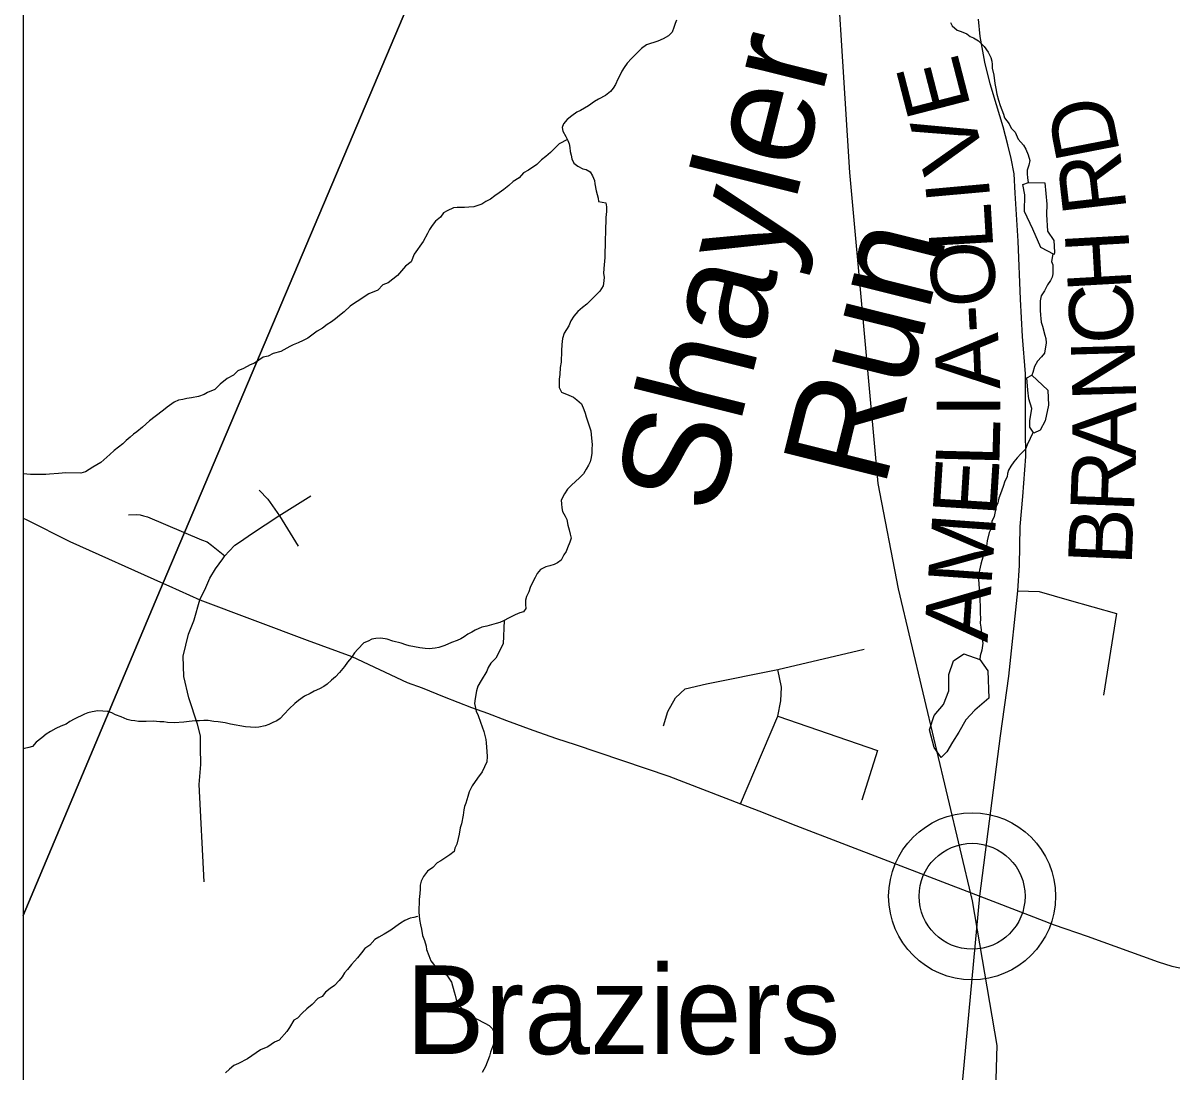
# Model space of a CAD drawing. Extents: x 0 to 34, y 0 to 22.
# Drawn here: x 2.1 to 3.128, y 15.954 to 16.889 of the extents above; entities that cross this region are included whole.
import ezdxf

# ---------------------------------------------------------------- set-up
doc = ezdxf.new("R2010")
doc.units = 0
for name, color, linetype in [('GM_X_Corporation', 7, 'Continuous'), ('GM_X_County_Road', 7, 'Continuous'), ('GM_X_County_Road_Text', 7, 'Continuous'), ('GM_X_Minor_Lake', 7, 'Continuous'), ('GM_X_Minor_River', 7, 'Continuous'), ('GM_X_Minor_River_Text', 7, 'Continuous'), ('GM_X_Rail_Line', 7, 'Continuous'), ('GM_X_Township_Road', 7, 'Continuous'), ('GM_X_Unincorporated', 7, 'Continuous'), ('GM_X_Unincorporated_Location', 7, 'Continuous'), ('GM_X_Unincorporated_Text', 7, 'Continuous'), ('SH_Data', 7, 'Continuous')]:
    doc.layers.add(name, color=color, linetype=linetype)

msp = doc.modelspace()

# ---------------------------------------------------------------- linework, layer by layer
at = {"layer": 'GM_X_Corporation'}
for points in [[(2.1, 20.9), (2.1, 16.0934), (2.225, 16.3897), (2.7544, 17.639), (2.811, 17.7726), (2.8255, 17.8068), (2.8709, 17.914), (2.886, 17.9497), (2.8909, 17.9612), (2.9719, 18.1533), (3.7872, 20.088)], [(3.7872, 20.088), (2.9719, 18.1533), (2.8909, 17.9612), (2.886, 17.9497), (2.8709, 17.914), (2.8255, 17.8068), (2.811, 17.7726), (2.7544, 17.639), (2.225, 16.3897), (2.1, 16.0934), (2.1, 14.8365)]]:
    msp.add_lwpolyline(points, dxfattribs=at)
at = {"layer": 'GM_X_County_Road'}
for points in [[(2.953, 16.1107), (2.9713, 16.2535), (2.9786, 16.3067), (2.9868, 16.3825), (2.9883, 16.4053), (2.9889, 16.4399), (2.9913, 16.4668), (2.9939, 16.5023), (2.9936, 16.5265), (2.9936, 16.576), (2.9909, 16.6092), (2.9892, 16.6426), (2.9872, 16.6943), (2.9843, 16.737), (2.9835, 16.7541), (2.9808, 16.7677), (2.9778, 16.78), (2.9736, 16.7961), (2.9676, 16.8156), (2.9621, 16.8344), (2.9574, 16.8538), (2.9532, 16.8765), (2.9518, 16.8919)], [(2.1, 16.4475), (2.1029, 16.4462), (2.1416, 16.4265), (2.2252, 16.3892), (2.2298, 16.3871)], [(2.2298, 16.3871), (2.2576, 16.3747), (2.3533, 16.3387), (2.393, 16.3242), (2.4425, 16.3011), (2.4557, 16.2962), (2.4755, 16.2881), (2.4998, 16.2786), (2.5139, 16.2735), (2.531, 16.2671), (2.5545, 16.2586), (2.5755, 16.251), (2.5922, 16.2458), (2.6756, 16.2174), (2.7395, 16.193), (2.7558, 16.1866), (2.7889, 16.1737), (2.953, 16.1107)], [(2.8829, 15.4935), (2.8842, 15.5063), (2.8874, 15.5358), (2.894, 15.5961), (2.8994, 15.6456), (2.9147, 15.7602), (2.9206, 15.7916), (2.9222, 15.8054), (2.9252, 15.8145), (2.9273, 15.8275), (2.9285, 15.8425), (2.9327, 15.8893), (2.9339, 15.9077), (2.9364, 15.9344), (2.953, 16.1107)], [(2.953, 16.1107), (2.997, 16.0938), (3.0192, 16.0852), (3.0486, 16.0749), (3.1119, 16.0522), (3.1239, 16.0483), (3.1311, 16.0466)]]:
    msp.add_lwpolyline(points, dxfattribs=at)
at = {"layer": 'GM_X_Minor_Lake'}
for points in [[(2.9927, 16.7207), (2.993, 16.7355), (2.9912, 16.7446), (2.9962, 16.7465)], [(2.996, 16.7465), (3.0107, 16.7462), (3.0126, 16.7272), (3.0124, 16.718), (3.0133, 16.7032), (3.0189, 16.6948), (3.0195, 16.6845), (3.0191, 16.6822), (3.0074, 16.6885), (3, 16.705), (2.9927, 16.7207)], [(2.9975, 16.5341), (2.9992, 16.545), (2.9967, 16.5538), (2.9957, 16.5614), (2.9947, 16.5725), (2.9993, 16.5748)], [(2.9993, 16.5748), (3.0135, 16.5615), (3.0141, 16.5482), (3.0112, 16.5342), (3.0068, 16.5259), (3.0011, 16.523), (2.9974, 16.5284), (2.9975, 16.5341)], [(2.9528, 16.3215), (2.9601, 16.3114), (2.9608, 16.287), (2.9485, 16.2762), (2.9403, 16.2676), (2.9341, 16.2567), (2.9286, 16.2477), (2.9235, 16.2391), (2.9185, 16.2342), (2.9121, 16.2431), (2.9079, 16.2587), (2.9123, 16.2716), (2.9204, 16.2813), (2.9252, 16.2934), (2.9254, 16.3082)], [(2.9254, 16.3082), (2.9295, 16.3202), (2.9387, 16.3265), (2.9528, 16.3215)]]:
    msp.add_lwpolyline(points, dxfattribs=at)
at = {"layer": 'GM_X_Minor_River'}
for points in [[(2.6825, 16.8911), (2.6814, 16.8881), (2.6802, 16.8847), (2.6786, 16.8805), (2.6755, 16.8771), (2.6705, 16.8746), (2.6659, 16.8724), (2.6556, 16.8691), (2.6513, 16.8658), (2.6475, 16.862), (2.6424, 16.8568), (2.6386, 16.8527), (2.6358, 16.8489), (2.6339, 16.8456), (2.6319, 16.8418), (2.6303, 16.8384), (2.628, 16.8339), (2.626, 16.8305), (2.6237, 16.8275), (2.6191, 16.8241), (2.6129, 16.8208), (2.6095, 16.8186), (2.6041, 16.8149), (2.5968, 16.8105), (2.5937, 16.809), (2.5891, 16.806), (2.5849, 16.8027), (2.5818, 16.7986), (2.5806, 16.7955), (2.5813, 16.7921), (2.5839, 16.7875), (2.5857, 16.784), (2.5868, 16.781), (2.5875, 16.7776), (2.5878, 16.7741), (2.5885, 16.7707), (2.5892, 16.7676), (2.5911, 16.7638), (2.5944, 16.7611), (2.599, 16.7587), (2.602, 16.7579), (2.6054, 16.756)], [(2.9266, 16.8891), (2.9281, 16.886), (2.9326, 16.8822), (2.9363, 16.8809), (2.9412, 16.879), (2.9443, 16.8766), (2.9473, 16.8754), (2.9518, 16.8727), (2.9566, 16.8677), (2.9604, 16.8627), (2.9626, 16.8577), (2.9637, 16.8546), (2.964, 16.8516), (2.9639, 16.8482), (2.9653, 16.842), (2.9664, 16.8348), (2.967, 16.8302), (2.9681, 16.8253), (2.9695, 16.8199), (2.971, 16.815), (2.9724, 16.8111), (2.9739, 16.8073), (2.975, 16.8042), (2.9791, 16.7988), (2.9809, 16.795), (2.9843, 16.7912), (2.9872, 16.785), (2.9917, 16.7796), (2.9939, 16.7762), (2.9961, 16.7712), (2.9975, 16.7662), (2.9967, 16.762), (2.9951, 16.7575), (2.995, 16.7541), (2.9954, 16.7507), (2.996, 16.7465)], [(2.5853, 16.7849), (2.578, 16.7808), (2.5703, 16.7733), (2.5661, 16.7696), (2.5622, 16.7666), (2.558, 16.7625), (2.5507, 16.7573), (2.5461, 16.7551), (2.5422, 16.7506), (2.5368, 16.7473), (2.5329, 16.7439), (2.5287, 16.7402), (2.5245, 16.7372), (2.5206, 16.7346), (2.5168, 16.7317), (2.5126, 16.7294), (2.5091, 16.7272), (2.5018, 16.7247), (2.4973, 16.7244), (2.4935, 16.7241), (2.487, 16.7242), (2.4836, 16.7239), (2.4782, 16.7213), (2.4747, 16.7195), (2.472, 16.7157), (2.4678, 16.712), (2.4647, 16.7082), (2.4623, 16.7045), (2.4604, 16.7011), (2.4568, 16.6939), (2.4487, 16.6827), (2.4459, 16.6759), (2.4409, 16.6718), (2.4339, 16.6635), (2.4254, 16.6572), (2.4208, 16.6554), (2.4162, 16.6505), (2.4081, 16.6473), (2.4031, 16.6439), (2.3993, 16.6413), (2.3962, 16.6395), (2.3916, 16.6362), (2.3862, 16.6313), (2.382, 16.628), (2.3785, 16.625), (2.375, 16.6224), (2.3712, 16.6198), (2.367, 16.6168), (2.3623, 16.6139), (2.3539, 16.6079), (2.3497, 16.6057), (2.3451, 16.6035), (2.3408, 16.6017), (2.3378, 16.6002), (2.3297, 16.5958), (2.3229, 16.594), (2.3186, 16.5918), (2.3141, 16.5908), (2.3064, 16.5856), (2.3025, 16.5841), (2.2964, 16.5808), (2.2914, 16.5786), (2.2876, 16.5749), (2.2818, 16.5719), (2.2756, 16.5667), (2.271, 16.5619), (2.2645, 16.5593), (2.2614, 16.5575), (2.2564, 16.5557), (2.2503, 16.5546), (2.2461, 16.5539), (2.2423, 16.5532), (2.2385, 16.5525), (2.2347, 16.5507), (2.2285, 16.5463), (2.2251, 16.5437), (2.2177, 16.5381), (2.2127, 16.534), (2.2066, 16.5284), (2.2015, 16.5243), (2.1985, 16.5221), (2.1954, 16.5195), (2.1919, 16.5165), (2.1888, 16.5135), (2.1811, 16.5076), (2.1773, 16.5042), (2.1692, 16.4971), (2.1622, 16.4927), (2.1557, 16.4886), (2.1515, 16.4876), (2.1382, 16.4878), (2.1317, 16.4871), (2.1237, 16.4865), (2.1203, 16.4862), (2.1066, 16.4864), (2.1002, 16.4869), (2.1, 16.487)], [(2.6054, 16.756), (2.6076, 16.7525), (2.6094, 16.7483), (2.6098, 16.7452), (2.6108, 16.7391), (2.6126, 16.7326), (2.6129, 16.7296), (2.6163, 16.7288), (2.6194, 16.7283), (2.6201, 16.7249), (2.62, 16.7207), (2.6195, 16.7154), (2.6193, 16.7025), (2.6188, 16.6953), (2.6186, 16.6797), (2.6176, 16.6698), (2.6175, 16.6653), (2.6179, 16.6622), (2.6178, 16.6588), (2.617, 16.6543), (2.6142, 16.6497), (2.6077, 16.643), (2.6026, 16.6382), (2.5988, 16.6352), (2.5945, 16.6315), (2.5911, 16.6273), (2.5883, 16.6232), (2.5864, 16.6187), (2.5824, 16.6123), (2.5808, 16.6074), (2.5804, 16.6021), (2.5799, 16.5964), (2.5797, 16.5865), (2.5789, 16.5816), (2.5784, 16.5755), (2.578, 16.5713), (2.5778, 16.5637), (2.58, 16.5595), (2.5865, 16.5571), (2.5906, 16.5551), (2.5936, 16.5528), (2.5977, 16.5493), (2.5999, 16.5443), (2.601, 16.5409), (2.6021, 16.5378), (2.6032, 16.534), (2.605, 16.5287), (2.6061, 16.5252), (2.6064, 16.5218), (2.6067, 16.5187), (2.6074, 16.513), (2.6069, 16.5089), (2.6069, 16.5054), (2.6064, 16.5013), (2.6056, 16.4975), (2.604, 16.4945), (2.6021, 16.4911), (2.5997, 16.4869), (2.5959, 16.4832), (2.5889, 16.4769), (2.5854, 16.4731), (2.5827, 16.469), (2.5796, 16.4633), (2.5799, 16.4603), (2.5802, 16.4565), (2.5809, 16.4534), (2.5831, 16.4492), (2.5846, 16.4462), (2.5857, 16.4412), (2.5867, 16.437), (2.5878, 16.4332), (2.5885, 16.4297), (2.5873, 16.426), (2.5853, 16.4211), (2.5841, 16.4177), (2.5822, 16.4147), (2.5798, 16.4101), (2.5763, 16.4075), (2.5733, 16.4061), (2.5695, 16.405), (2.566, 16.4039), (2.5614, 16.4017), (2.5583, 16.398), (2.5564, 16.3946), (2.554, 16.3901), (2.552, 16.3855), (2.5508, 16.3818), (2.5489, 16.3776), (2.548, 16.3742), (2.548, 16.3704), (2.5483, 16.367), (2.546, 16.364), (2.5429, 16.3629), (2.5387, 16.3614), (2.5333, 16.3585), (2.5283, 16.3559), (2.5249, 16.3545), (2.5218, 16.3534), (2.5134, 16.3512), (2.5089, 16.3502), (2.5031, 16.3476)], [(3.0179, 16.6829), (3.0169, 16.6762), (3.018, 16.6731)], [(3.018, 16.6731), (3.0179, 16.6682), (3.0179, 16.6651), (3.0174, 16.6621), (3.0159, 16.6591), (3.0132, 16.6553), (3.0104, 16.65), (3.0077, 16.6455), (3.0068, 16.641), (3.0067, 16.6326), (3.007, 16.6284), (3.0073, 16.6254), (3.0076, 16.622), (3.0087, 16.6185), (3.0109, 16.6105), (3.0116, 16.6075), (3.0119, 16.6036), (3.0106, 16.5945), (3.0079, 16.5912), (3.0044, 16.5874), (3.0017, 16.5825), (3.0001, 16.5772), (2.9993, 16.5748)], [(3.0004, 16.524), (2.9952, 16.5127), (2.9936, 16.5089), (2.9893, 16.5048), (2.9862, 16.5011), (2.9831, 16.4977), (2.9804, 16.4936), (2.9784, 16.4902), (2.9776, 16.4872), (2.9772, 16.4841), (2.9752, 16.4804), (2.9736, 16.4755), (2.9712, 16.469), (2.9697, 16.4653), (2.9688, 16.4611), (2.9673, 16.4577), (2.9656, 16.449), (2.9636, 16.4445), (2.9635, 16.4407), (2.9627, 16.4376), (2.9612, 16.4346), (2.9595, 16.4271), (2.9587, 16.4225), (2.9575, 16.4191), (2.9547, 16.4097), (2.9538, 16.4063), (2.9526, 16.401), (2.9518, 16.3964), (2.9517, 16.3926), (2.952, 16.3888), (2.9526, 16.3801), (2.953, 16.3762), (2.9532, 16.3671), (2.9531, 16.3629), (2.9534, 16.3576), (2.9533, 16.3538), (2.9537, 16.3504), (2.955, 16.3393), (2.9557, 16.3359), (2.9548, 16.3298), (2.9532, 16.3246), (2.9528, 16.3215)], [(2.5289, 16.3562), (2.528, 16.3354), (2.5213, 16.3226), (2.5171, 16.3181), (2.5147, 16.3144), (2.5135, 16.311), (2.5084, 16.3027), (2.5053, 16.2978), (2.5041, 16.2936), (2.5029, 16.2868), (2.5024, 16.2823), (2.5038, 16.2754), (2.5056, 16.2716), (2.5078, 16.2655), (2.5107, 16.2574), (2.5125, 16.2502), (2.5128, 16.2471), (2.5135, 16.2395), (2.5138, 16.2349), (2.5133, 16.2304), (2.5094, 16.2213), (2.5051, 16.2157), (2.5004, 16.209), (2.4977, 16.2037), (2.4964, 16.1995), (2.4948, 16.1935), (2.4936, 16.1905), (2.4928, 16.1874), (2.4924, 16.1829), (2.4907, 16.1749), (2.4895, 16.1715), (2.4887, 16.1658), (2.4878, 16.1621), (2.4866, 16.1568), (2.485, 16.1534), (2.4842, 16.1503), (2.4804, 16.1474), (2.4723, 16.1422), (2.4692, 16.1403), (2.4654, 16.1362), (2.4604, 16.1329), (2.4569, 16.128), (2.4549, 16.1239), (2.4541, 16.1205), (2.454, 16.1167), (2.4536, 16.1129), (2.4531, 16.1076), (2.4529, 16.0962), (2.4535, 16.0897), (2.4542, 16.0851), (2.4553, 16.0813), (2.456, 16.0756), (2.4578, 16.071), (2.4592, 16.066), (2.4596, 16.063), (2.4618, 16.0576), (2.4636, 16.053), (2.4658, 16.05), (2.4695, 16.0453), (2.4744, 16.0418), (2.4778, 16.0402), (2.4819, 16.0341), (2.4844, 16.0253), (2.4851, 16.0223), (2.4862, 16.0184), (2.4876, 16.0146), (2.4906, 16.0115), (2.4959, 16.0057), (2.5011, 16.0026), (2.5042, 16.0014), (2.5117, 15.9975), (2.5155, 15.9955), (2.5185, 15.9924), (2.521, 15.9863), (2.5209, 15.9825), (2.5186, 15.9764), (2.5166, 15.9715), (2.5158, 15.9681), (2.5122, 15.9587), (2.5094, 15.9534)], [(2.5031, 16.3476), (2.5, 16.3458), (2.4966, 16.3439), (2.4931, 16.3417), (2.4901, 16.3399), (2.487, 16.3384), (2.482, 16.3366), (2.4759, 16.334), (2.4705, 16.3322), (2.4675, 16.3315), (2.4621, 16.3309), (2.4584, 16.3313), (2.4538, 16.3318), (2.4489, 16.3326), (2.4443, 16.3335), (2.4413, 16.3346), (2.4371, 16.3359), (2.4296, 16.3379), (2.4247, 16.3395), (2.419, 16.3404), (2.4144, 16.3401), (2.411, 16.3397), (2.4075, 16.3379), (2.4037, 16.3364), (2.3983, 16.3308), (2.3956, 16.3275), (2.3928, 16.3233), (2.3893, 16.3192), (2.3866, 16.3151), (2.382, 16.3098), (2.3785, 16.3061), (2.375, 16.3031), (2.3711, 16.2994), (2.3681, 16.2975), (2.3642, 16.2953), (2.3596, 16.2931), (2.3558, 16.2913), (2.3508, 16.2887), (2.3454, 16.285), (2.3423, 16.2824), (2.3373, 16.2776), (2.3327, 16.2727), (2.3292, 16.269), (2.3261, 16.2667), (2.3227, 16.2653), (2.3192, 16.2634), (2.3158, 16.2624), (2.3101, 16.2613), (2.307, 16.261), (2.3028, 16.2611), (2.2983, 16.2615), (2.285, 16.2637), (2.2801, 16.2649), (2.274, 16.2658), (2.2702, 16.2662), (2.2649, 16.2671), (2.2611, 16.2671), (2.2573, 16.2668), (2.2535, 16.2669), (2.2482, 16.2662), (2.2432, 16.2655), (2.2348, 16.2649), (2.2288, 16.2654), (2.2254, 16.2658), (2.2219, 16.2659), (2.2189, 16.2663), (2.2159, 16.2664), (2.2098, 16.2661), (2.2029, 16.2662), (2.1995, 16.2667), (2.1965, 16.2671), (2.1927, 16.2679), (2.1874, 16.2703), (2.1825, 16.2723), (2.1791, 16.2739), (2.1757, 16.2751), (2.1711, 16.2755), (2.1666, 16.2756), (2.1616, 16.2749), (2.1578, 16.2739), (2.1548, 16.2728), (2.1456, 16.2684), (2.1417, 16.2662), (2.1383, 16.2639), (2.1337, 16.2621), (2.1291, 16.2599), (2.1245, 16.2573), (2.1206, 16.2548), (2.1168, 16.2518), (2.1118, 16.2477), (2.1083, 16.244), (2.1052, 16.2432), (2.1014, 16.2422), (2.1, 16.2419)], [(2.4517, 16.0924), (2.4483, 16.0917), (2.4452, 16.091), (2.4402, 16.0888), (2.4364, 16.0866), (2.4322, 16.0836), (2.4279, 16.0803), (2.4218, 16.0766), (2.4172, 16.074), (2.4137, 16.0721), (2.4091, 16.0669), (2.4048, 16.0639), (2.4017, 16.0602), (2.3982, 16.0557), (2.3928, 16.0497), (2.3893, 16.0452), (2.3866, 16.0422), (2.3846, 16.0388), (2.3819, 16.0355), (2.3777, 16.031), (2.3738, 16.0284), (2.3696, 16.025), (2.3665, 16.0213), (2.3627, 16.0195), (2.3576, 16.0142), (2.353, 16.0101), (2.3487, 16.0064), (2.3445, 16.0019), (2.3414, 16.0001), (2.3375, 15.9937), (2.3352, 15.9899), (2.3282, 15.9824), (2.324, 15.9806), (2.3182, 15.9765), (2.3117, 15.9736), (2.3002, 15.9658), (2.2921, 15.9614), (2.2879, 15.9596), (2.284, 15.9566), (2.2806, 15.9532)]]:
    msp.add_lwpolyline(points, dxfattribs=at)
at = {"layer": 'GM_X_Rail_Line'}
msp.add_lwpolyline([(2.7988, 17.139), (2.8205, 17.0146), (2.8367, 16.7553), (2.8621, 16.4782), (2.88, 16.3843), (2.946, 16.1063), (2.9681, 15.9775), (2.9632, 15.8168), (2.9604, 15.4067), (2.9714, 15.0477), (3.006, 14.6804), (3.0102, 14.5176), (3.0299, 14.3321), (3.0382, 14.2206), (3.0407, 14.1566), (3.0308, 14.1)], dxfattribs=at)
at = {"layer": 'GM_X_Township_Road'}
for points in [[(2.2576, 16.3747), (2.2629, 16.3855), (2.2665, 16.3939), (2.2714, 16.4021), (2.2781, 16.4112), (2.28, 16.4139), (2.2836, 16.418), (2.2889, 16.4232), (2.2939, 16.4266), (2.3037, 16.4334), (2.3157, 16.4414), (2.3281, 16.4494), (2.3564, 16.4674)], [(2.3105, 16.4724), (2.3182, 16.4644), (2.3285, 16.4495), (2.3453, 16.4225)], [(2.194, 16.4505), (2.201, 16.4506), (2.2044, 16.4503), (2.2073, 16.4496), (2.2108, 16.4486), (2.2592, 16.4282), (2.264, 16.4262), (2.268, 16.4234), (2.28, 16.4139)], [(2.9868, 16.3825), (3.0059, 16.3821), (3.0326, 16.3744), (3.0746, 16.3625), (3.063, 16.2897)], [(2.2522, 16.3558), (2.2525, 16.3567), (2.2576, 16.3747)], [(2.2614, 16.1235), (2.257, 16.21), (2.2584, 16.2279), (2.2582, 16.243), (2.2583, 16.2535), (2.2556, 16.2637), (2.2477, 16.2872), (2.2434, 16.3063), (2.2427, 16.3243), (2.2475, 16.3439), (2.2522, 16.3558)], [(2.6708, 16.2623), (2.6747, 16.2752), (2.6817, 16.2873), (2.6901, 16.2954), (2.7092, 16.2999), (2.7728, 16.3125), (2.8498, 16.3307)], [(2.7395, 16.193), (2.7728, 16.271), (2.7756, 16.2845), (2.7761, 16.2968), (2.7728, 16.3125)], [(2.7728, 16.271), (2.8616, 16.2405), (2.8476, 16.1962)]]:
    msp.add_lwpolyline(points, dxfattribs=at)
at = {"layer": 'GM_X_Unincorporated'}
for radius in [0.0744, 0.0472]:
    msp.add_circle((2.946, 16.1105), radius, dxfattribs=at)
at = {"layer": 'GM_X_Unincorporated_Location'}
msp.add_line((2.946, 16.1105), (2.946, 16.1105), dxfattribs=at)
at = {"layer": 'SH_Data'}
msp.add_line((2.1, 20.9), (2.1, 14.1), dxfattribs=at)

# ---------------------------------------------------------------- texts
at = {"layer": 'GM_X_County_Road_Text'}
for s, rotation, p in [('E', 104.4759, (2.9452, 16.8135)), ('D', 100.9733, (3.078, 16.7729)), ('V', 105.3115, (2.9583, 16.7655)), ('R', 96.5689, (3.084, 16.7218)), ('I', 95.144, (2.9624, 16.7314)), ('L', 93.3826, (2.965, 16.6871)), ('O', 93.2086, (2.9678, 16.6369)), ('H', 93.2331, (3.0883, 16.6508)), ('C', 93.0483, (3.0908, 16.604)), ('-', 93.1626, (2.9691, 16.6136)), ('A', 92.2845, (2.9711, 16.5627)), ('N', 91.6809, (3.0923, 16.5525)), ('I', 90.2631, (2.9713, 16.5372)), ('A', 89.5119, (3.0919, 16.5002)), ('L', 88.5631, (2.9702, 16.4928)), ('E', 86.3957, (2.9674, 16.4481)), ('R', 87.903, (3.0902, 16.4518)), ('M', 86.0173, (2.9631, 16.3862)), ('B', 87.4662, (3.0881, 16.4047)), ('A', 86.0153, (2.9597, 16.3363))]:
    msp.add_text(s, height=0.0568, rotation=rotation, dxfattribs=at).set_placement(p)
at = {"layer": 'GM_X_Minor_River_Text'}
for s, rotation, p in [('Shayler', 75.997, (2.7186, 16.4484)), ('Run', 75.9969, (2.8676, 16.4727))]:
    msp.add_text(s, height=0.09465, rotation=rotation, dxfattribs=at).set_placement(p)
at = {"layer": 'GM_X_Unincorporated_Text'}
msp.add_text('Braziers', height=0.07898, rotation=0, dxfattribs=at).set_placement((2.4411, 15.9699))

doc.saveas('drawing.dxf')
